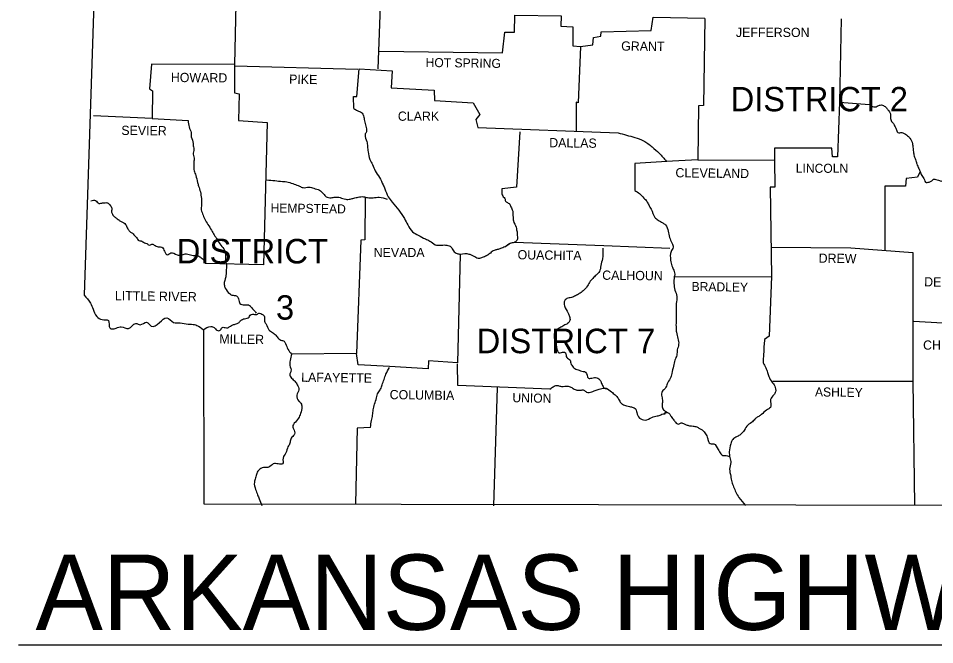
# Model space of a CAD drawing. Extents: x -42408 to 34530, y -43140 to 20491.
# Drawn here: x -42408 to -40066, y 17164 to 18766 of the extents above; entities that cross this region are included whole.
import ezdxf

# ---------------------------------------------------------------- set-up
doc = ezdxf.new("R2010")
doc.units = 0
for name, color, linetype in [('1', 7, 'Continuous'), ('2', 7, 'Continuous'), ('3', 7, 'Continuous')]:
    doc.layers.add(name, color=color, linetype=linetype)

msp = doc.modelspace()

# ---------------------------------------------------------------- linework, layer by layer
at = {"layer": '1'}
msp.add_line((-42408, 17163.6), (-38820.6, 17163.6), dxfattribs=at)
for points in [[(-42304, 20465.7), (-42190, 19551), (-42239.6, 18057.9)], [(-41476.8, 18979.2), (-41489.4, 18636.4)], [(-41849.9, 18918.7), (-41856, 18647.9), (-42067.9, 18648.5), (-42072.8, 18585.7), (-42065.1, 18580.2), (-42065.7, 18509.8), (-42215.9, 18516.4)], [(-41485.6, 18682), (-41170.8, 18677.6), (-41164.7, 18729.9), (-41140, 18729.9), (-41139.4, 18773.9), (-41020.5, 18772.3), (-41021.6, 18745.9), (-40990.8, 18743.7), (-40990.8, 18695.2), (-40971, 18693.6)], [(-40971, 18693.6), (-40940.2, 18698), (-40938, 18716.7), (-40919.8, 18720), (-40918.7, 18731), (-40790.5, 18734.9), (-40785.5, 18768.4), (-40654, 18766.2)], [(-40654, 18765.1), (-40657.3, 18542.8), (-40670, 18542.2), (-40671.6, 18404.1)], [(-40305.1, 18764.6), (-40309.5, 18551.6), (-40233, 18545.6)], [(-40971, 18693.6), (-40977.6, 18549.4), (-40982.6, 18551.1), (-40982, 18476.2)], [(-41856, 18647.9), (-41856, 18574.7), (-41843.9, 18572.5), (-41845, 18504.3), (-41772.3, 18498.8), (-41781.1, 18135), (-41930.8, 18138.8)], [(-41854.9, 18644.1), (-41540.1, 18635.8)], [(-41550.5, 18535.1), (-41551.6, 18565.4), (-41542.8, 18565.9), (-41537.3, 18636.9), (-41452.6, 18631.4), (-41454.8, 18587.9), (-41345.2, 18581.9), (-41344.7, 18555.5), (-41245.6, 18549.4), (-41228.6, 18519.7), (-41239, 18506.5), (-41234.1, 18486.1), (-40875.2, 18472.9)], [(-40309.5, 18551.6), (-40314.4, 18411.8), (-40327.1, 18411.8), (-40329.3, 18433.3), (-40475.7, 18433.3), (-40475.7, 18402.5)], [(-42065.7, 18509.8), (-41974.3, 18504.3)], [(-41126.2, 18475.7), (-41134.5, 18334.2), (-41172.4, 18329.8)], [(-40750.9, 18399.2), (-40832.3, 18394.2), (-40832.9, 18325.4)], [(-40671.6, 18404.1), (-40752, 18399.2)], [(-40671.6, 18404.1), (-40476.8, 18403)], [(-40475.7, 18403), (-40475.1, 18334.2), (-40486.7, 18333.7), (-40483.4, 18105.3)], [(-40103.6, 18373.8), (-40110.2, 18359), (-40139.4, 18356.2), (-40141.1, 18336.4), (-40193.3, 18336.4), (-40193.9, 18171.9)], [(-41521.4, 18308.9), (-41522.5, 18199.4), (-41532.4, 18198.3), (-41543.4, 17908.2)], [(-41140, 18192.8), (-40912.1, 18184.5), (-40743.2, 18177.9)], [(-40485, 18180.1), (-40280.9, 18178.5), (-40122.4, 18166.4)], [(-41278.6, 18162), (-41285.8, 17884.6), (-41360.1, 17889.5), (-41360.6, 17869.2), (-41459.7, 17875.2)], [(-40122.4, 18166.4), (-40122.4, 17837.2), (-40118, 17520.8)], [(-40732.1, 18104.7), (-40483.4, 18105.3)], [(-40483.4, 18105.3), (-40488.9, 17952.3), (-40501, 17944.6)], [(-40119.6, 17990.8), (-40045.9, 17986.4), (-40042.6, 17954.5), (-39976, 17956.7), (-39973.2, 17983.6), (-39960.5, 17983.6)], [(-41935.2, 17969.3), (-41934.1, 17524.1), (-39917.1, 17520.8)], [(-41459.7, 17875.2), (-41539.5, 17879.6), (-41543.4, 17908.2), (-41710.1, 17906.6)], [(-41049.7, 17817.4), (-41284.7, 17826.2), (-41285.8, 17881.8)], [(-41184.5, 17821.3), (-41193.3, 17519.1)], [(-40480.1, 17837.8), (-40122.4, 17837.8)], [(-41508.1, 17719.5), (-41542.3, 17717.3), (-41546.1, 17523.5)]]:
    msp.add_lwpolyline(points, dxfattribs=at)
for points in [[(-41550.5, 18535.1), (-41541.7, 18529.6), (-41531.3, 18524.6), (-41525.8, 18516.4), (-41523.6, 18503.7), (-41519.7, 18490), (-41518.6, 18475.7), (-41521.9, 18468), (-41517.5, 18450.3), (-41515.8, 18438.2), (-41514.2, 18423.9), (-41509.8, 18404.7), (-41502.6, 18391.5), (-41496, 18375.5), (-41485, 18358.4), (-41475.7, 18339.7), (-41471.3, 18329.8), (-41463, 18309.5), (-41452.6, 18295.7), (-41436, 18274.8), (-41421.2, 18253.3), (-41412.9, 18237.4), (-41400.3, 18219.7), (-41386, 18210.9), (-41367.8, 18201.6), (-41356.2, 18196.1), (-41343, 18186.7), (-41326, 18185.6), (-41313.3, 18185.6), (-41301.8, 18180.7), (-41296.3, 18170.8), (-41286.4, 18164.2), (-41278.6, 18162)], [(-40233, 18545.6), (-40224.7, 18540), (-40213.2, 18540.6), (-40205.5, 18543.9), (-40199.4, 18543.4), (-40191.1, 18538.4), (-40185.6, 18531.8), (-40181.8, 18526.8), (-40179, 18519.1), (-40179, 18512), (-40176.3, 18502.1), (-40173, 18498.2), (-40168.6, 18491.1), (-40165.8, 18484.5), (-40164.2, 18480.1), (-40158.1, 18472.9), (-40152.6, 18473.5), (-40147.7, 18472.9), (-40141.1, 18469.1), (-40131.2, 18461.3), (-40129.5, 18459.1), (-40122.9, 18444.8), (-40121.8, 18436), (-40120.7, 18424.5), (-40118.5, 18413.5), (-40114.1, 18401.4), (-40111.9, 18393.1), (-40106.9, 18381.5), (-40103.6, 18373.8), (-40099.2, 18363.9), (-40092.6, 18352.9), (-40089.9, 18346.3), (-40080.5, 18346.9), (-40073.9, 18349.6), (-40069, 18354), (-40062.9, 18353.5), (-40056.3, 18351.3), (-40047.5, 18349.6), (-40042, 18352.9), (-40039.3, 18355.1), (-40038.7, 18360.1), (-40033.7, 18362.8), (-40028.2, 18359), (-40022.2, 18350.2), (-40022.2, 18344.7), (-40024.4, 18341.4), (-40031.5, 18337), (-40041.5, 18333.7), (-40044.2, 18329.8), (-40034.8, 18325.4), (-40020, 18324.3), (-40016.1, 18327.6), (-40006.2, 18324.9), (-40002.4, 18327.6), (-39989.2, 18327.1), (-39983.1, 18331.5), (-39971, 18330.9), (-39967.2, 18328.2), (-39967.2, 18323.2), (-39957.2, 18321), (-39950.1, 18322.7), (-39940.7, 18319.9), (-39932.5, 18315.5), (-39928.1, 18309.5), (-39922.6, 18302.8), (-39917.6, 18304.5), (-39913.8, 18309.5), (-39905.5, 18318.3), (-39905.5, 18323.8), (-39903.3, 18327.6), (-39900.6, 18333.1)], [(-41974.3, 18504.3), (-41971.5, 18487.8), (-41966.6, 18473.5), (-41966, 18462.4), (-41961.1, 18445.9), (-41961.1, 18439.9), (-41959.4, 18427.8), (-41961.6, 18421.2), (-41958.9, 18408), (-41959.4, 18398.1), (-41959.4, 18389.8), (-41958.9, 18376), (-41954.5, 18363.9), (-41950.1, 18345.8), (-41947.3, 18336.4), (-41942.9, 18322.1), (-41940.2, 18304.5), (-41939.6, 18291.3), (-41940.7, 18279.2), (-41937.4, 18265.4), (-41931.4, 18251.7), (-41923.7, 18238.5), (-41914.3, 18223.6), (-41907.7, 18212), (-41899.4, 18199.4), (-41892.8, 18188.9), (-41882.9, 18175.7), (-41878.5, 18164.7), (-41878.5, 18149.3), (-41876.3, 18135), (-41876.9, 18119), (-41878, 18104.7), (-41881.8, 18084.9), (-41879.1, 18075.5), (-41868.6, 18061.8), (-41862, 18057.9), (-41850.5, 18055.7), (-41845, 18048), (-41841.7, 18036.5), (-41830.1, 18032.6), (-41817.4, 18031.5), (-41811.4, 18024.9), (-41803.1, 18016.1), (-41800.4, 18011.7)], [(-40875.2, 18472.9), (-40832.3, 18460.8), (-40810.3, 18452.5), (-40788.3, 18436.6), (-40770.1, 18420.6), (-40752, 18400.3)], [(-41773.4, 18352.4), (-41752.5, 18350.7), (-41733.2, 18348.5), (-41718.4, 18346.9), (-41703, 18341.4), (-41689.2, 18336.4), (-41680.4, 18332.6), (-41665.5, 18333.7), (-41652.9, 18330.9), (-41638.6, 18326), (-41628.1, 18316.6), (-41621.5, 18309.5), (-41608.9, 18306.7), (-41598.4, 18308.3), (-41585.7, 18307.2), (-41571.4, 18302.8), (-41559.9, 18303.4), (-41550.5, 18305.6), (-41539.5, 18308.3), (-41525.8, 18309.5), (-41515.3, 18307.2), (-41501.5, 18306.7), (-41485.6, 18308.3), (-41465.8, 18302.8)], [(-41172.4, 18329.8), (-41172.4, 18319.4), (-41168.6, 18309.5), (-41164.7, 18305), (-41163.1, 18297.9), (-41158.1, 18294.6), (-41151, 18288), (-41147.1, 18278.6), (-41144.4, 18272.6), (-41144.4, 18264.9), (-41143.8, 18257.2), (-41142.7, 18247.8), (-41136.1, 18231.3), (-41134.5, 18224.7), (-41133.4, 18219.2), (-41132.8, 18209.8), (-41132.8, 18198.8), (-41140, 18192.8)], [(-40832.9, 18325.4), (-40820.2, 18317.2), (-40809.7, 18306.1), (-40802, 18297.9), (-40797.1, 18288.5), (-40790.5, 18277.5), (-40781.1, 18256.6), (-40772.9, 18249.5), (-40761.3, 18242.3), (-40754.2, 18237.4), (-40747, 18221.4), (-40743.7, 18205.4), (-40737.6, 18191.1), (-40734.9, 18180.1), (-40739.9, 18169.1), (-40741, 18147.1), (-40737.6, 18132.2), (-40733.2, 18121.2), (-40730.5, 18108.6), (-40732.1, 18104.7)], [(-42222.5, 18299), (-42210.4, 18299.5), (-42202.1, 18292.4), (-42197.2, 18292.9), (-42188.4, 18294), (-42180.1, 18293.5), (-42174.1, 18288.5), (-42169.1, 18279.7), (-42169.7, 18271.5), (-42169.1, 18268.2), (-42165.3, 18261), (-42158.7, 18255.5), (-42151.5, 18250), (-42144.9, 18245.6), (-42133.9, 18238.5), (-42132.8, 18236.3), (-42128.4, 18227.4), (-42122.9, 18220.3), (-42116.3, 18215.9), (-42109.1, 18208.2), (-42105.8, 18204.9), (-42100.3, 18197.2), (-42094.3, 18196.6), (-42086, 18191.7), (-42080, 18190), (-42073.4, 18185.6), (-42066.8, 18187.8), (-42058.5, 18184.5), (-42047.5, 18181.2), (-42041.4, 18180.1), (-42034.3, 18169.7), (-42027.1, 18160.9), (-42018.3, 18165.8), (-42001.8, 18160.9), (-41991.4, 18160.3), (-41982, 18163.1), (-41974.8, 18162.5), (-41961.6, 18159.2), (-41953.4, 18159.2), (-41944.6, 18155.9), (-41936.3, 18149.3), (-41930.8, 18142.1), (-41930.8, 18138.8)], [(-41150.4, 18190.6), (-41164.7, 18181.2), (-41175.7, 18176.8), (-41184, 18174.1), (-41191.7, 18171.9), (-41201.6, 18165.3), (-41209.3, 18159.8), (-41219.8, 18154.8), (-41229.7, 18151.5), (-41241.8, 18155.4), (-41248.4, 18159.2), (-41255.5, 18162), (-41278.6, 18162)], [(-41164.7, 18181.2), (-41150.4, 18190.6), (-41140, 18192.8)], [(-40914.3, 18177.9), (-40915.4, 18150.4), (-40919.3, 18133.3), (-40923.1, 18117.9), (-40931.4, 18109.1), (-40940.2, 18100.3), (-40948.4, 18090.4), (-40955.6, 18078.3), (-40962.7, 18070.6), (-40972.1, 18062.9), (-40981.5, 18057.4), (-40991.9, 18052.4), (-41003.5, 18049.7), (-41011.7, 18043.6), (-41012.3, 18030.4), (-41002.9, 18011.7), (-40999.6, 18002.9), (-40998.5, 17992.4), (-41002.4, 17986.4), (-41011.2, 17981.4), (-41021.6, 17975.4), (-41031, 17969.9), (-41037.6, 17960.5), (-41038.7, 17947.9), (-41034.3, 17933), (-41032.6, 17924.2), (-41025.5, 17910.4), (-41020, 17911), (-41010.1, 17910.4), (-41009, 17907.7), (-41008.4, 17904.9), (-41006.2, 17897.8), (-40998, 17891.7), (-40996.9, 17886.2), (-40991.9, 17875.8), (-40983.7, 17868.6), (-40977.6, 17866.4), (-40964.9, 17862.6), (-40958.3, 17860.9), (-40951.2, 17845), (-40942.4, 17845.5), (-40935.8, 17846.6), (-40924.8, 17843.9), (-40919.8, 17837.2), (-40914.9, 17826.2), (-40908.3, 17818.5), (-40903.9, 17818.5)], [(-40732.1, 18104.7), (-40729.9, 18070.6), (-40725, 18054.1), (-40726.6, 18036.5), (-40727.2, 18019.4), (-40727.2, 18004), (-40727.2, 17989.1), (-40727.2, 17973.7), (-40726.1, 17962.7), (-40722.2, 17946.8), (-40720.6, 17931.9), (-40723.9, 17917.6), (-40725.5, 17904.4), (-40729.9, 17891.2), (-40733.8, 17876.3), (-40738.2, 17857.1), (-40742.1, 17844.4), (-40749.8, 17831.2), (-40754.7, 17819.1), (-40762.4, 17811.4), (-40763.5, 17798.2), (-40761.9, 17786.1), (-40763, 17775.1), (-40759.1, 17764.6), (-40749.2, 17757.4)], [(-42239.6, 18057.9), (-42223.6, 18037), (-42217, 18022.2), (-42207.6, 18002.9), (-42193.9, 17995.2), (-42177.9, 17992.4), (-42174.6, 17973.7), (-42158.1, 17973.2), (-42144.9, 17977), (-42126.7, 17972.1), (-42107.5, 17985.3), (-42096.5, 17982), (-42080.5, 17988.6), (-42068.4, 17978.7), (-42047.5, 17987.5), (-42028.8, 17999.6), (-42011.2, 17988), (-41994.1, 17986.4), (-41973.7, 17983.6), (-41957.8, 17982.5), (-41943.5, 17975.4), (-41933, 17968.2), (-41935.2, 17969.3)], [(-41935.2, 17969.3), (-41916, 17977.6), (-41907.7, 17974.8), (-41900.5, 17967.7), (-41892.3, 17967.7), (-41887.9, 17974.3), (-41879.6, 17974.8), (-41873, 17974.3), (-41865.9, 17978.7), (-41859.8, 17981.4), (-41851.6, 17984.2), (-41845.5, 17986.4), (-41840, 17992.4), (-41830.1, 17997.4), (-41818.5, 18001.3), (-41815.2, 18006.8), (-41809.7, 18009), (-41798.7, 18008.4), (-41791.6, 18011.7), (-41785.5, 18009), (-41780, 18005.1), (-41778.9, 17990.8), (-41774.5, 17983.1), (-41767.9, 17969.3), (-41758.6, 17962.2), (-41749.7, 17955), (-41746.4, 17950.6), (-41737.1, 17942.4), (-41728.8, 17939.6), (-41725, 17933.6), (-41718.9, 17919.2), (-41710.1, 17906.6)], [(-40501, 17944.6), (-40502.6, 17927.5), (-40503.2, 17911.5), (-40504.3, 17896.1), (-40504.3, 17884.6), (-40497.7, 17871.9), (-40493.8, 17859.8), (-40490, 17849.4), (-40482.3, 17835.6), (-40475.1, 17825.1), (-40472.9, 17810.3), (-40477.3, 17802.6), (-40485.6, 17791), (-40486.1, 17770.1), (-40496, 17763.5), (-40508.7, 17752.5), (-40515.9, 17747.5), (-40523.6, 17742.6), (-40531.8, 17733.8), (-40543.9, 17725.5), (-40552.7, 17711.8), (-40562.6, 17701.3), (-40570.9, 17695.8), (-40582.4, 17688.7), (-40587.4, 17677.6), (-40591.3, 17657.3), (-40589.6, 17642.4), (-40587.4, 17629.2), (-40590.2, 17612.7), (-40587.4, 17594.5), (-40584.7, 17580.2), (-40580.2, 17567.6), (-40574.2, 17553.3), (-40566.5, 17540.1), (-40550, 17519.7)], [(-41710.1, 17906.6), (-41713.4, 17890.6), (-41714, 17878), (-41711.2, 17863.1), (-41714, 17856), (-41709.6, 17845.5), (-41701.3, 17837.2), (-41695.3, 17828.4), (-41691.4, 17815.8), (-41696.4, 17801.5), (-41690.9, 17786.6), (-41685.9, 17781.1), (-41683.2, 17772.3), (-41687, 17755.2), (-41692, 17742.6), (-41703, 17729.9), (-41706.3, 17723.9), (-41704.6, 17715.6), (-41701.9, 17702.4), (-41704.6, 17698.6), (-41711.8, 17689.2), (-41714, 17678.7), (-41718.9, 17669.9), (-41724.4, 17654), (-41731.6, 17640.8), (-41732.7, 17625.9), (-41743.7, 17625.9), (-41756.4, 17625.9), (-41767.9, 17617.7), (-41778.4, 17617.1), (-41791, 17612.2), (-41798.7, 17601.7), (-41801.5, 17590.1), (-41804.8, 17579.1), (-41801.5, 17560.4), (-41796.5, 17547.2), (-41792.7, 17536.8), (-41786.1, 17519.7)], [(-41508.1, 17719.5), (-41505.4, 17737.1), (-41502.6, 17750.8), (-41501, 17764), (-41497.7, 17778.9), (-41492.7, 17794.9), (-41488.3, 17808.1), (-41482.3, 17817.4), (-41478.4, 17828.4), (-41473.5, 17841.6), (-41468.5, 17855.4), (-41459.7, 17873)], [(-41049.7, 17817.4), (-41040.9, 17823.5), (-41032.6, 17826.8), (-41024.4, 17825.1), (-41015.6, 17824), (-41007.9, 17825.1), (-40998, 17823.5), (-40989.7, 17818.5), (-40980.4, 17814.7), (-40971, 17814.7), (-40962.7, 17814.7), (-40955.6, 17809.7), (-40942.4, 17810.3), (-40931.4, 17814.7), (-40920.4, 17818), (-40905.5, 17819.6), (-40892.3, 17810.3), (-40882.9, 17802.6), (-40875.2, 17793.8), (-40869.7, 17783.9), (-40863.7, 17778.4), (-40853.8, 17774.5), (-40846.1, 17772.9), (-40836.7, 17770.1), (-40831.8, 17767.9), (-40827.4, 17757.4), (-40820.2, 17743.1), (-40806.4, 17738.2), (-40789.4, 17744.8), (-40775.6, 17748.6), (-40765.7, 17751.9), (-40759.7, 17754.1), (-40754.2, 17754.7), (-40755.8, 17755.8), (-40749.2, 17757.4), (-40743.2, 17753), (-40739.3, 17747), (-40732.7, 17738.2), (-40726.6, 17730.5), (-40720.6, 17727.7), (-40714.5, 17731), (-40706.3, 17728.3), (-40699.1, 17725.5), (-40690.9, 17723.3), (-40683.7, 17722.8), (-40674.4, 17720.6), (-40667.2, 17716.7), (-40660.6, 17712.9), (-40654, 17705.7), (-40647.4, 17694.7), (-40645.2, 17685.9), (-40637.5, 17677.1), (-40630.3, 17677.1), (-40619.9, 17662.8), (-40616, 17657.3), (-40607.8, 17647.4), (-40601.7, 17647.4), (-40590.2, 17645.2)]]:
    msp.add_spline(points, degree=3, dxfattribs=at)

# ---------------------------------------------------------------- texts
at = {"layer": '2'}
for s, height, p in [('JEFFERSON', 23.67, (-40574.2, 18717.8)), ('CLARK', 23.67, (-41438.1, 18503.6)), ('LINCOLN', 23.11, (-40421.2, 18370.5)), ('NEVADA', 23.67, (-41499.9, 18154.8)), ('CHICOT', 23.67, (-40095.9, 17918.1)), ('ARKANSAS HIGHWAY DISTRICT 1', 192.623, (-42364, 17201.6))]:
    msp.add_text(s, height=height, dxfattribs=at).set_placement(p)
for s, height, rotation, p in [('GRANT', 23.67, 359.4032, (-40867.5, 18683.1)), ('HOT SPRING', 23.11, 359.2216, (-41367.3, 18641.3)), ('HOWARD', 23.67, 359.5145, (-42018.3, 18602.8)), ('PIKE', 23.66, 359.0452, (-41716.2, 18598.4)), ('SEVIER', 23.67, 359.4271, (-42144.9, 18467.4)), ('DALLAS', 23.66, 359.2462, (-41051.4, 18436)), ('CLEVELAND', 23.67, 359.3377, (-40728.8, 18359)), ('HEMPSTEAD', 23.11, 359.1885, (-41763.5, 18269.3)), ('OUACHITA', 23.67, 359.2043, (-41132.3, 18149.3)), ('DREW', 23.66, 359.2258, (-40362.9, 18140.5)), ('CALHOUN', 23.67, 359.3634, (-40916, 18097)), ('DESHA', 23.66, 359.3704, (-40093.2, 18080)), ('BRADLEY', 23.11, 359.1449, (-40687.6, 18068.4)), ('LITTLE RIVER', 23.666, 359.1697, (-42161.4, 18044.7)), ('MILLER', 23.66, 359.1319, (-41894.5, 17934.1)), ('LAFAYETTE', 23.66, 359.1839, (-41685.4, 17836.1)), ('ASHLEY', 23.11, 359.2361, (-40372.2, 17798.7)), ('COLUMBIA', 23.66, 359.2125, (-41459.2, 17791.6)), ('UNION', 23.11, 358.9584, (-41145.5, 17783.9))]:
    msp.add_text(s, height=height, rotation=rotation, dxfattribs=at).set_placement(p)
at = {"layer": '3'}
for s, height, p in [('DISTRICT 2', 62.19, (-40587.4, 18527.9)), ('DISTRICT', 62.74, (-42003.3, 18138.7)), ('3', 62.2, (-41749.6, 17995.1)), ('DISTRICT 7', 62.74, (-41237, 17909.1))]:
    msp.add_text(s, height=height, dxfattribs=at).set_placement(p)

doc.saveas('drawing.dxf')
